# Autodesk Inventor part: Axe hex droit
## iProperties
Author: Flavien MARTY
Shininess: 60.0
PropertySet Name: _Private Model Information
Created: 2001-10
Part Number: Axe hex droit
Material: Par défaut
Document SubType Name: Modélisation
Designer: Flavien MARTY
Control State: 0
Master: False
Checked Out: False
PropertySet Name: Design Tracking Control
Density: 0.0
Volumn: 0.0
Area: 0.0
PropertySet Name: Model Information
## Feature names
1. Base1
